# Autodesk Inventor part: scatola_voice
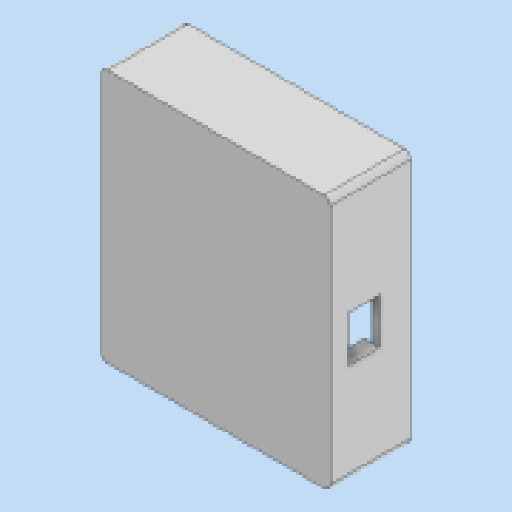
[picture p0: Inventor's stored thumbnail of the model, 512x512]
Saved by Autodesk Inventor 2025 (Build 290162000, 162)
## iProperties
Created: 2025-03
Part Number: scatola_voice
Material: Generico
Document SubType Name: Modeling
Designer: Ryzen5700u
Density: 1 g/cm^3
Appearance: Default
Author: Ryzen5700u
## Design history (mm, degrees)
sketch "Schizzo1"
  geometry: L1 (47.588, 12.346)-(-26.412, 12.346); L2 (-26.412, 12.346)-(-26.412, -69.654); L3 (-26.412, -69.654)-(47.588, -69.654); L4 (47.588, -69.654)-(47.588, 12.346); 1 further point
  constraints: 8 end point, 2 parallel, 1 horizontal, 1 perpendicular
  dimensions: "d0" = 74 distance of L3.end L2.end; "d1" = 82 distance of L2.end L1.end
extrude "Estrusione1" new body sketch "Schizzo1" distance "d2" = 6; taper "d3" = 0 deg
sketch "Schizzo2"
  geometry: L1 (-21.088, -17.654)-(-40.088, -17.654) reference; L2 (-40.088, -41.654)-(-21.088, -41.654) reference; L3 (-36.088, -41.854)-(-23.088, -41.854); L4 (-17.088, -17.454)-(-36.088, -17.454); L5 (-7.088, -14.654)-(-23.588, -14.654) reference; L6 (-3.088, -14.854)-(-19.588, -14.854); L7 (-47.588, -69.654)-(-47.588, 12.346) reference; L8 (-17.088, -17.454)-(-47.588, -17.454); L9 (-47.588, -17.454)-(-47.588, -14.885); L10 (-47.588, -14.885)-(-17.088, -14.885); L11 (-17.088, -14.885)-(-17.088, -17.454); L12 (-42.588, -20.154)-(-42.588, -23.654) reference; L13 (-42.588, -35.654)-(-42.588, -39.154) reference; L14 (-42.788, -20.154)-(-42.788, -22.534); L15 (-42.788, -22.534)-(-47.588, -22.534); L16 (-47.588, -22.534)-(-47.588, -17.454); L17 (-47.588, -17.454)-(-42.788, -17.454); L18 (-42.788, -17.454)-(-42.788, -22.534); L19 (-42.788, -37.278)-(-47.588, -37.278); L20 (-47.588, -37.278)-(-47.588, -44.457); L21 (-47.588, -44.457)-(-42.788, -44.457); L22 (-42.788, -44.457)-(-42.788, -37.278); L23 (-23.088, -41.854)-(-42.788, -41.854); L24 (-42.788, -41.854)-(-42.788, -44.457); L25 (-42.788, -44.457)-(-23.088, -44.457); L26 (-23.088, -44.457)-(-23.088, -41.854); L27 (-18.588, -39.154)-(-18.588, -20.154) reference; L28 (-18.388, -37.154)-(-18.388, -20.787); L29 (-18.388, -20.787)-(-16.888, -20.787); L30 (-16.888, -20.787)-(-16.888, -38.829); L31 (-16.888, -38.829)-(-18.388, -38.829); L32 (-18.388, -38.829)-(-18.388, -20.787); 15 further points
  constraints: 50 end point, 15 parallel, 5 horizontal, 5 perpendicular, 3 point on line
  dimensions: "d5" = 0.2 distance between parallel lines of L3 L2; "d6" = 0.2 distance between parallel lines of L1 L4; "d7" = 0.2 distance between parallel lines of L5 L6; "d8" = 0.2 distance between parallel lines of L12 L14; "d9" = 0.2 distance between parallel lines of L27 L28; "d10" = 1.5 distance of L30.end L31.end
extrude "Estrusione2" join sketch "Schizzo2" distance "d11" = 10; taper "d12" = 0 deg
extrude "Estrusione3" join sketch "Schizzo3" distance "d19" = 4; taper "d20" = 0 deg
fillet "Raccordo1" dims "d21" = 1
sketch "Schizzo4"
  geometry: C1 r 2.4 at (-16.588, -10.654) reference; C2 r 2.4 at (-16.588, 5.346) reference; C3 r 2.3 at (-16.588, 5.346); C4 r 2.3 at (-16.588, -10.654); 1 further point
  constraints: 2 centre point, 2 coincident
  dimensions: "d22" = 4.6 diameter of C3; "d23" = 4.6 diameter of C4
  node "Riferimento13"
  node "Riferimento14"
node "Piano di lavoro1"
extrude "Estrusione4" join sketch "Schizzo4" distance "d24" = 16; taper "d25" = 0 deg
sketch "Schizzo5"
  geometry: L1 (-42.788, -22.534)-(-47.588, -22.534) reference; L2 (-47.588, -37.278)-(-47.588, -22.534) reference; L3 (-47.588, -37.278)-(-42.788, -37.278) reference; L4 (-42.788, -37.278)-(-42.788, -41.854) reference; L5 (-42.788, -41.854)-(-23.088, -41.854) reference; L6 (-23.088, -41.854)-(-23.088, -44.457) reference; L7 (-23.088, -44.457)-(-47.588, -44.457) reference; L8 (-47.588, -69.654)-(-47.588, -44.457) reference; L9 (26.412, -69.654)-(-47.588, -69.654) reference; L10 (26.412, 12.346)-(26.412, -69.654) reference; L11 (-47.588, 12.346)-(26.412, 12.346) reference; L12 (-47.588, -14.885)-(-47.588, 12.346) reference; L13 (-47.588, -14.885)-(-17.088, -14.885) reference; L14 (-17.088, -14.885)-(-17.088, -17.454) reference; L15 (-17.088, -17.454)-(-42.788, -17.454) reference; L16 (-42.788, -17.454)-(-42.788, -22.534) reference; L17 (-16.888, -38.829)-(-18.388, -38.829) reference; L18 (-18.388, -38.829)-(-18.388, -20.787) reference; L19 (-18.388, -20.787)-(-16.888, -20.787) reference; L20 (-16.888, -20.787)-(-16.888, -38.829) reference; L21 (-47.588, 12.346)-(26.412, 12.346) reference; L22 (-47.588, 12.346)-(26.412, 12.346); L23 (26.412, 12.346)-(26.412, 9.846); L24 (26.412, 9.846)-(-47.588, 9.846); L25 (-47.588, 9.846)-(-47.588, 12.346); L26 (26.412, 12.346)-(23.912, 12.346); L27 (23.912, 12.346)-(23.912, -69.654); L28 (23.912, -69.654)-(26.412, -69.654); L29 (26.412, -69.654)-(26.412, 12.346); L30 (-47.588, 12.346)-(-45.088, 12.346); L31 (-45.088, 12.346)-(-45.088, -14.885); L32 (-45.088, -14.885)-(-47.588, -14.885); L33 (-47.588, -14.885)-(-47.588, 12.346); L34 (-47.588, -44.457)-(-45.088, -44.457); L35 (-45.088, -44.457)-(-45.088, -69.654); L36 (-45.088, -69.654)-(-47.588, -69.654); L37 (-47.588, -69.654)-(-47.588, -44.457); L38 (-47.588, -69.654)-(-16.588, -69.654); L39 (-16.588, -69.654)-(-16.588, -67.154); L40 (-16.588, -67.154)-(-47.588, -67.154); L41 (-47.588, -67.154)-(-47.588, -69.654); L42 (26.412, -69.654)-(-47.588, -69.654) reference; L43 (26.412, -69.654)-(20.412, -69.654); L44 (20.412, -69.654)-(20.412, -67.154); L45 (20.412, -67.154)-(26.412, -67.154); L46 (26.412, -67.154)-(26.412, -69.654); L47 (-45.088, 3.846)-(-39.088, 9.846); L48 (-45.088, 3.846)-(-36.603, 3.846); L49 (17.912, 9.846)-(23.912, 5.346); L50 (20.412, -67.154)-(23.912, -62.487); L51 (-39.088, -67.154)-(-45.088, -62.654); C1 r 2.3 at (-16.588, -10.654) reference; C2 r 2.3 at (-16.588, 5.346) reference; C3 r 2.5 at (17.371, -20.575) reference; C4 r 2.5 at (-13.667, -65.279) reference; C5 r 2.5 at (17.371, -65.279) reference; C6 r 2.5 at (-13.667, -20.575) reference; 8 further points
  constraints: 58 end point, 12 parallel, 12 point on line, 8 perpendicular, 7 horizontal, 1 equal length
  dimensions: "d26" = 2.5 distance of L22.end L23.end; "d27" = 2.5 distance of L28.end L27.end; "d28" = 2.5 distance of L31.end L32.end; "d29" = 2.5 distance of L35.end L36.end; "d30" = 2.5 distance of L39.end L38.end; "d31" = 6 distance of L44.end L45.end; "d34" = 45 deg angle of L48 L47; "d35" = 6 distance from line of L31 L47.end; "d36" = 6 distance from line of L27 L49.start; "d37" = 6 distance from line of L35 L51.start
extrude "Estrusione5" join sketch "Schizzo5" distance "d32" = 20; taper "d33" = 0 deg
fillet "Raccordo2" dims "d38" = 2
sketch "Schizzo6"
  geometry: L1 (-47.588, 10.346)-(-47.588, -14.885) reference; L2 (24.412, 12.346)-(-45.588, 12.346) reference; L3 (26.412, -67.654)-(26.412, 10.346) reference; L4 (-45.588, -69.654)-(-16.588, -69.654) reference; L5 (-47.588, -44.457)-(-47.588, -67.654) reference; 5 further points
  dimensions: "d39" = 3 distance from line of L1 point (-44.588, 9.346); "d40" = 3 distance from line of L2 point (-44.588, 9.346); "d41" = 3 distance from line of L2 point (23.412, 9.346); "d42" = 3 distance from line of L3 point (23.412, 9.346); "d43" = 3 distance from line of L4 point (-44.588, -66.654); "d44" = 3 distance from line of L5 point (-44.588, -66.654); "d45" = 3 distance from line of L3 point (23.412, -66.654)
hole "Foro1" sketch "Schizzo6" at (-44.588, 9.346), (23.412, 9.346), (-44.588, -66.654), (23.412, -66.654) diameter "d46" = 2; stored, may be unused: countersink angle "d50" = 90 deg, drill point angle "d52" = 118 deg; dims "d47" = 6, "d48" = 4, "d49" = 2, "d51" = 8
sketch "Schizzo7"
  geometry: L1 (-17.088, -14.885)-(-45.088, -14.885) reference; L2 (-47.588, -44.457)-(-45.088, -44.457) reference; L3 (-45.088, -14.885)-(-47.588, -14.885); L4 (-47.588, -14.885)-(-47.588, -44.457); L5 (-47.588, -44.457)-(-45.088, -44.457); L6 (-45.088, -44.457)-(-45.088, -14.885); 2 further points
  constraints: 8 end point, 2 parallel, 1 horizontal, 1 perpendicular
extrude "Estrusione6" join sketch "Schizzo7" stored distance "d53" = 20; taper "d54" = 0 deg
sketch "Schizzo8"
  geometry: L1 (19.412, -9.654)-(19.412, 4.346) reference; L2 (-7.088, -14.654)-(14.412, -14.654) reference; L3 (14.412, 9.346)-(-7.088, 9.346) reference; L4 (-23.588, 9.346)-(-7.088, 9.346) reference; L5 (-7.088, -14.654)-(-23.588, -14.654) reference; L6 (-28.588, -9.654)-(-28.588, -7.654) reference; L7 (-28.588, -7.654)-(-28.588, 2.346) reference; L8 (-28.588, 2.346)-(-28.588, 4.346) reference; L9 (-23.588, 9.346)-(-7.088, 9.346) reference; A1 r 5 centre (14.412, 4.346) between (19.412, 4.346) and (14.412, 9.346) reference; A2 r 5 centre (14.412, -9.654) between (14.412, -14.654) and (19.412, -9.654) reference; A3 r 5 centre (-23.588, -9.654) between (-28.588, -9.654) and (-23.588, -14.654) reference; A4 r 5 centre (-23.588, 4.346) between (-23.588, 9.346) and (-28.588, 4.346) reference; 1 further point
extrude "Estrusione7" join sketch "Schizzo8" distance "d55" = 8; taper "d56" = 0 deg
node "Solido1"
node "Riferimento1"
node "Riferimento2"
node "Riferimento3"
node "Riferimento4"
node "Riferimento5"
node "Riferimento6"
node "Linea chiusa proiettata2"
node "Riferimento15"
node "Riferimento16"
node "Riferimento17"
node "Riferimento18"
node "Riferimento19"
node "Riferimento20"
node "Riferimento21"
node "Riferimento22"
node "Riferimento23"
node "Riferimento24"
node "Riferimento25"
node "Riferimento26"
node "Riferimento27"
other parameters: "d13" = 3, "d14" = 3, "d15" = 3, "d16" = 3, "d17" = 4.6, "d18" = 4.6
